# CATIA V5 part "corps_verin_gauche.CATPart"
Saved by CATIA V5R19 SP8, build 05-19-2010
Part number: corps_verin_gauche
Bounding box of the stored display mesh (mm): x -775 to -575, y -59.975 to 59.975, z 75 to 1200
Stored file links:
  G:\EU_thinkMotion\CFAO_2010\MMS_groupe2\MMS_groupe2\OK\mmartini\mmartiniCFAO\corps_verin_gauche.CATPart
  C:\Users\Mathieu Martini\Desktop\CFAO\Animation\CFAO.CATProduct
  G:\EU_thinkMotion\CFAO_2010\MMS_groupe2\MMS_groupe2\OK\mmartini\mmartiniCFAO\Squelette.CATPart
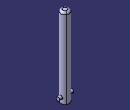
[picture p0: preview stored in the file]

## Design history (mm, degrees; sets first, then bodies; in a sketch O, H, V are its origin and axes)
External parameters (linked from other documents)
  External.diametre_canon = 150 mm
  External.diametre_verin = 120 mm
AxisSystem1: origin (0, 0, 0), X (1, 0, 0), Y (0, 1, 0), Z (0, 0, 1)
Set1
  Sketch1 on Plane1, origin (-675, 0, 0), H (0, 1, 0), V (0, 0, 1)
    line L1 (0, 1200) -> (60, 1200)
    line L2 (60, 1200) -> (60, 75)
    line L3 (60, 75) -> (0, 75)
    line L4 (0, 75) -> (0, 1200)
    point P5 (0, 150)
    reference projected point E1 (0, 150) from Point1
    length L1 = 60 {= External.diametre_verin /2}
    distance P5 L3 = 75 {= External.diametre_canon /2}
    distance P5 L1 = 1050 {= External.diametre_canon *7}
    horizontal: L1 H, L3 H
    vertical: L2 V, L4 V
    coincidence: P5 L4, P5 E1
Set2
  Plane1 "Plan_verin_gauche": linked copy from another document
  Point1 "pt_canonvertical": linked copy from another document
  Point2 "Point_verin_gauche": linked copy from another document
Body1 (main body)
  Shaft1: profile Sketch1, axis Sketch1.L4, angle 360
  Fillet1: radius 30 {= External.diametre_verin /4}, on edge [face of Shaft1 from Sketch1.L1 | face of Shaft1 from Sketch1.L2]
  Sketch2 on Plane1, origin (-675, 0, 0), H (0, 1, 0), V (0, 0, 1)
    circle A1 centre (0, 150) radius 24
    point P1 (0, 150)
    reference projected point E1 (0, 150) from Point1
    radius A1 = 24 {= External.diametre_verin  /5}
    coincidence: P1 E1
  Pad1: profile Sketch2, direction (1, 0, 0), length 100 {= External.diametre_canon /1.5}, opposite side length 100 {= External.diametre_canon /1.5}
  Sketch3 on face of Shaft1 from Sketch1.L3, origin (0, 0, 75), H (1, 0, 0), V (0, -1, 0)
    circle A1 centre (-675, 0) radius 48
    point P1 (-675, 0)
    reference projected point E1 (-675, 0) from Point2
    radius A1 = 48 {= (External.diametre_verin -External.diametre_verin /5)/2}
    coincidence: P1 E1
  Pocket1: profile Sketch3, direction (0, 0, 1), length 1012.5 {= External.diametre_canon *6.75}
